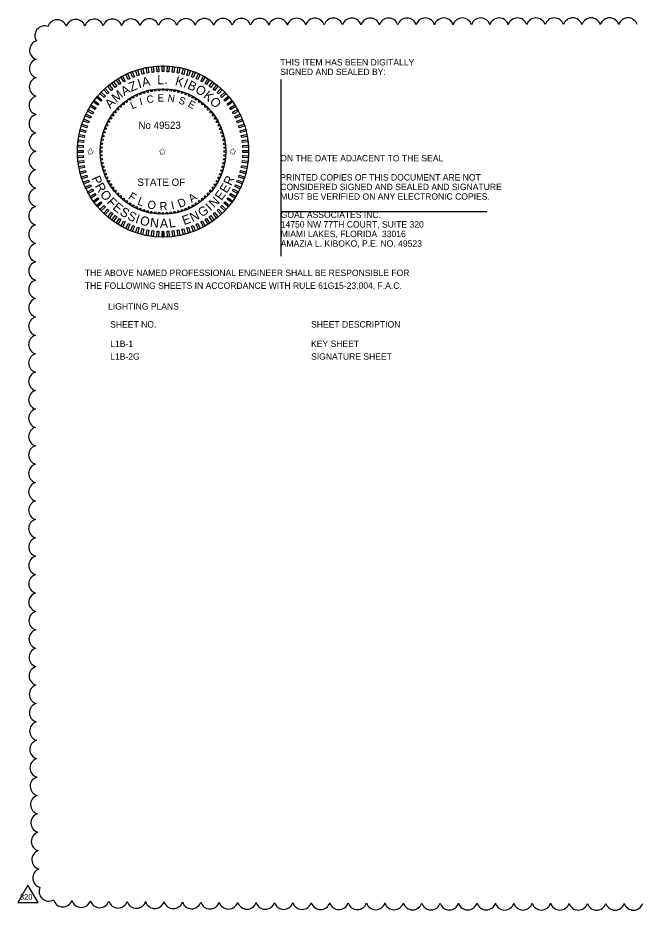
# Model space of a CAD drawing. Extents: x -811.2 to -767.6, y -2295.2 to -2235.1.
# Drawn here: x -783.8 to -777.02, y -2269.67 to -2259.9 of the extents above; entities that cross this region are included whole.
import ezdxf

# ---------------------------------------------------------------- set-up
doc = ezdxf.new("R2010")
doc.units = 0
for name, color, linetype in [('AdhocPoint_dp', 7, 'Continuous'), ('Cloud_dp', 7, 'Continuous'), ('PlotBorder_dp', 7, 'Continuous'), ('TextMinor', 7, 'Continuous'), ('TextMisc', 7, 'Continuous'), ('TextShtNo', 7, 'Continuous')]:
    doc.layers.add(name, color=color, linetype=linetype)

msp = doc.modelspace()

# ---------------------------------------------------------------- linework, layer by layer
at = {"layer": 'AdhocPoint_dp'}
for p, q in [((-780.9186, -2260.5734), (-780.9186, -2262.5081)), ((-780.9186, -2262.0181), (-778.6618, -2262.0181))]:
    msp.add_line(p, q, dxfattribs=at)
at = {"layer": 'Cloud_dp'}
msp.add_lwpolyline([(-783.6889, -2269.3954), (-783.7966, -2269.5835), (-783.576, -2269.5835)], close=True, dxfattribs=at)
for centre, start, end in [((-782.5594, -2260.0139), 17.87787, 162.87787), ((-782.3579, -2260.0127), 17.82689, 162.82689), ((-782.1564, -2260.0116), 17.78716, 162.78716), ((-781.9548, -2260.0107), 17.75505, 162.75505), ((-781.7533, -2260.0098), 17.72841, 162.72841), ((-781.5518, -2260.009), 17.70584, 162.70584), ((-781.3502, -2260.0084), 17.6864, 162.6864), ((-781.1487, -2260.0077), 17.66942, 162.66942), ((-780.9472, -2260.0072), 17.65443, 162.65443), ((-780.7456, -2260.0066), 17.64106, 162.64106), ((-780.5441, -2260.0062), 17.62905, 162.62905), ((-780.3425, -2260.0057), 17.61817, 162.61817), ((-780.141, -2260.0053), 17.60826, 162.60826), ((-779.9394, -2260.005), 17.59919, 162.59919), ((-779.7379, -2260.0046), 17.59084, 162.59084), ((-779.5364, -2260.0043), 17.58312, 162.58312), ((-779.3348, -2260.004), 17.57595, 162.57595), ((-779.1333, -2260.0038), 17.56928, 162.56928), ((-778.9317, -2260.0036), 17.56305, 162.56305), ((-778.7302, -2260.0033), 17.55721, 162.55721), ((-778.5286, -2260.0032), 17.55172, 162.55172), ((-778.3271, -2260.003), 17.54655, 162.54655), ((-778.1255, -2260.0028), 17.54167, 162.54167), ((-777.924, -2260.0027), 17.53705, 162.53705), ((-777.7224, -2260.0026), 17.53267, 162.53267), ((-777.5209, -2260.0025), 17.52851, 162.52851), ((-777.3194, -2260.0024), 17.52455, 162.52455), ((-777.1178, -2260.0023), 17.52079, 162.52079), ((-783.5053, -2260.0909), 68.43954, 213.43954), ((-783.3652, -2260.0225), 18.59454, 163.59454), ((-783.1638, -2260.0193), 18.21421, 163.21421), ((-782.9624, -2260.0171), 18.04696, 163.04696), ((-782.7609, -2260.0154), 17.94666, 162.94666), ((-783.563, -2260.2503), 106.80445, 251.80445), ((-783.565, -2260.4517), 107.04367, 252.04367), ((-783.5664, -2260.6532), 107.15618, 252.15618), ((-783.5675, -2260.8547), 107.22533, 252.22533), ((-783.5684, -2261.0562), 107.27338, 252.27338), ((-783.5691, -2261.2578), 107.30928, 252.30928), ((-783.5697, -2261.4593), 107.33743, 252.33743), ((-783.5703, -2261.6608), 107.36027, 252.36027), ((-783.5707, -2261.8624), 107.37928, 252.37928), ((-783.5711, -2262.0639), 107.39543, 252.39543), ((-783.5715, -2262.2655), 107.40937, 252.40937), ((-783.5717, -2262.467), 107.42156, 252.42156), ((-783.572, -2262.6685), 107.43234, 252.43234), ((-783.5722, -2262.8701), 107.44197, 252.44197), ((-783.5724, -2263.0716), 107.45063, 252.45063), ((-783.5726, -2263.2732), 107.45847, 252.45847), ((-783.5727, -2263.4747), 107.46563, 252.46563), ((-783.5728, -2263.6763), 107.47218, 252.47218), ((-783.5729, -2263.8778), 107.47822, 252.47822), ((-783.573, -2264.0794), 107.4838, 252.4838), ((-783.573, -2264.2809), 107.48899, 252.48899), ((-783.5731, -2264.4824), 107.49382, 252.49382), ((-783.5731, -2264.684), 107.49843, 252.49843), ((-783.573, -2264.8855), 107.51148, 252.51148), ((-783.573, -2265.0871), 107.53101, 252.53101), ((-783.5728, -2265.2886), 107.55191, 252.55191), ((-783.5726, -2265.4901), 107.57435, 252.57435), ((-783.5723, -2265.6917), 107.59852, 252.59852), ((-783.5719, -2265.8932), 107.62468, 252.62468), ((-783.5714, -2266.0947), 107.65309, 252.65309), ((-783.5708, -2266.2963), 107.68411, 252.68411), ((-783.5701, -2266.4978), 107.71817, 252.71817), ((-783.5693, -2266.6993), 107.75578, 252.75578), ((-783.5683, -2266.9009), 107.79762, 252.79762), ((-783.5672, -2267.1024), 107.84454, 252.84454), ((-783.5659, -2267.3039), 107.89767, 252.89767), ((-783.5644, -2267.5054), 107.95851, 252.95851), ((-783.5626, -2267.7069), 108.02912, 253.02912), ((-783.5606, -2267.9084), 108.11243, 253.11243), ((-783.5583, -2268.1099), 108.21279, 253.21279), ((-783.5556, -2268.3113), 108.33694, 253.33694), ((-783.5523, -2268.5128), 108.49611, 253.49611), ((-783.5485, -2268.7142), 108.71068, 253.71068), ((-783.5437, -2268.9155), 109.02298, 254.02298), ((-783.5374, -2269.1166), 109.54201, 254.54201), ((-783.5282, -2269.3173), 110.71007, 255.71007), ((-783.4585, -2269.4643), 155.06518, 300.06518), ((-783.3038, -2269.5272), 195.62937, 340.62937), ((-783.1027, -2269.5327), 196.26473, 341.26473), ((-782.9013, -2269.5365), 196.54985, 341.54985), ((-782.6999, -2269.5396), 196.72204, 341.72204), ((-782.4984, -2269.5421), 196.84059, 341.84059), ((-782.2969, -2269.5443), 196.92865, 341.92865), ((-782.0954, -2269.5461), 196.99739, 341.99739), ((-781.8939, -2269.5478), 197.053, 342.053), ((-781.6924, -2269.5493), 197.09919, 342.09919), ((-781.4909, -2269.5506), 197.13834, 342.13834), ((-781.2893, -2269.5519), 197.17209, 342.17209), ((-781.0878, -2269.553), 197.20158, 342.20158), ((-780.8863, -2269.554), 197.22762, 342.22762), ((-780.6847, -2269.5549), 197.25085, 342.25085), ((-780.4832, -2269.5557), 197.27174, 342.27174), ((-780.2817, -2269.5565), 197.29065, 342.29065), ((-780.0801, -2269.5572), 197.30788, 342.30788), ((-779.8786, -2269.5578), 197.32367, 342.32367), ((-779.6771, -2269.5584), 197.3382, 342.3382), ((-779.4755, -2269.559), 197.35163, 342.35163), ((-779.274, -2269.5595), 197.3641, 342.3641), ((-779.0724, -2269.5599), 197.37571, 342.37571), ((-778.8709, -2269.5604), 197.38657, 342.38657), ((-778.6693, -2269.5607), 197.39674, 342.39674), ((-778.4678, -2269.5611), 197.40629, 342.40629), ((-778.2663, -2269.5614), 197.4153, 342.4153), ((-778.0647, -2269.5617), 197.4238, 342.4238), ((-777.8632, -2269.5619), 197.43184, 342.43184), ((-777.6616, -2269.5622), 197.43947, 342.43947), ((-777.4601, -2269.5624), 197.44671, 342.44671), ((-777.2585, -2269.5625), 197.4536, 342.4536), ((-777.057, -2269.5627), 197.46017, 342.46017)]:
    msp.add_arc(centre, 0.1057, start, end, dxfattribs=at)
at = {"layer": 'TextMinor'}
for radius in [0.9375, 0.6875]:
    msp.add_circle((-782.2078, -2261.3603), radius, dxfattribs=at)
at = {"layer": 'TextShtNo'}
for p, q in [((-782.2178, -2262.2978), (-782.218, -2262.2353)), ((-782.2078, -2262.2978), (-782.208, -2262.2353)), ((-782.1978, -2262.2978), (-782.198, -2262.2353))]:
    msp.add_line(p, q, dxfattribs=at)
for points in [[(-782.5205, -2260.543), (-782.5392, -2260.5504), (-782.5622, -2260.4923), (-782.5434, -2260.4849)], [(-782.4685, -2260.525), (-782.4877, -2260.5312), (-782.507, -2260.4718), (-782.4878, -2260.4656)], [(-782.4156, -2260.5102), (-782.4351, -2260.5152), (-782.4506, -2260.4548), (-782.4311, -2260.4498)], [(-782.3618, -2260.4989), (-782.3816, -2260.5026), (-782.3933, -2260.4413), (-782.3735, -2260.4375)], [(-782.3074, -2260.4909), (-782.3274, -2260.4934), (-782.3352, -2260.4315), (-782.3152, -2260.4289)], [(-782.2526, -2260.4864), (-782.2727, -2260.4876), (-782.2767, -2260.4253), (-782.2565, -2260.424)], [(-782.1976, -2260.4853), (-782.2178, -2260.4853), (-782.2178, -2260.4228), (-782.1976, -2260.4228)], [(-782.1427, -2260.4876), (-782.1629, -2260.4864), (-782.1589, -2260.4241), (-782.1388, -2260.4253)], [(-782.088, -2260.4934), (-782.1081, -2260.4909), (-782.1002, -2260.429), (-782.0802, -2260.4315)], [(-782.0338, -2260.5027), (-782.0537, -2260.4989), (-782.042, -2260.4376), (-782.0221, -2260.4413)], [(-781.9803, -2260.5153), (-781.9999, -2260.5103), (-781.9844, -2260.4498), (-781.9648, -2260.4548)], [(-781.9277, -2260.5312), (-781.9469, -2260.525), (-781.9276, -2260.4656), (-781.9084, -2260.4719)], [(-781.8762, -2260.5505), (-781.895, -2260.543), (-781.872, -2260.485), (-781.8532, -2260.4924)], [(-782.6681, -2260.616), (-782.6851, -2260.6268), (-782.7186, -2260.5741), (-782.7015, -2260.5633)], [(-782.6204, -2260.5886), (-782.6381, -2260.5983), (-782.6682, -2260.5436), (-782.6505, -2260.5339)], [(-782.5712, -2260.5642), (-782.5894, -2260.5728), (-782.616, -2260.5163), (-782.5978, -2260.5077)], [(-781.826, -2260.5729), (-781.8443, -2260.5643), (-781.8177, -2260.5078), (-781.7994, -2260.5164)], [(-781.7773, -2260.5984), (-781.795, -2260.5887), (-781.7649, -2260.534), (-781.7473, -2260.5437)], [(-781.7303, -2260.6269), (-781.7474, -2260.6161), (-781.7139, -2260.5634), (-781.6969, -2260.5742)], [(-782.7994, -2260.7155), (-782.8141, -2260.7293), (-782.8568, -2260.6838), (-782.8421, -2260.6699)], [(-782.7577, -2260.6796), (-782.7733, -2260.6925), (-782.8131, -2260.6443), (-782.7975, -2260.6315)], [(-782.7139, -2260.6464), (-782.7302, -2260.6583), (-782.7669, -2260.6078), (-782.7506, -2260.5959)], [(-781.6852, -2260.6584), (-781.7016, -2260.6465), (-781.6649, -2260.596), (-781.6485, -2260.6079)], [(-781.6422, -2260.6926), (-781.6578, -2260.6797), (-781.618, -2260.6316), (-781.6024, -2260.6445)], [(-781.6014, -2260.7294), (-781.6161, -2260.7156), (-781.5734, -2260.6701), (-781.5586, -2260.6839)], [(-782.8755, -2260.7947), (-782.8884, -2260.8102), (-782.9365, -2260.7704), (-782.9237, -2260.7549)], [(-782.8387, -2260.7539), (-782.8525, -2260.7686), (-782.898, -2260.7258), (-782.8842, -2260.7111)], [(-781.563, -2260.7687), (-781.5768, -2260.754), (-781.5313, -2260.7113), (-781.5175, -2260.726)], [(-781.5271, -2260.8104), (-781.54, -2260.7948), (-781.4919, -2260.755), (-781.479, -2260.7706)], [(-782.9412, -2260.8828), (-782.952, -2260.8999), (-783.0047, -2260.8664), (-782.9939, -2260.8494)], [(-782.9097, -2260.8377), (-782.9216, -2260.8541), (-782.9721, -2260.8174), (-782.9603, -2260.801)], [(-781.4939, -2260.8542), (-781.5058, -2260.8379), (-781.4553, -2260.8012), (-781.4434, -2260.8175)], [(-781.4635, -2260.9), (-781.4744, -2260.883), (-781.4216, -2260.8495), (-781.4108, -2260.8666)], [(-782.9952, -2260.9785), (-783.0038, -2260.9968), (-783.0603, -2260.9702), (-783.0517, -2260.9519)], [(-782.9697, -2260.9298), (-782.9794, -2260.9475), (-783.0341, -2260.9174), (-783.0244, -2260.8997)], [(-781.4361, -2260.9477), (-781.4458, -2260.93), (-781.3911, -2260.8999), (-781.3814, -2260.9176)], [(-781.4117, -2260.9969), (-781.4203, -2260.9787), (-781.3638, -2260.9521), (-781.3552, -2260.9704)], [(-783.0369, -2261.0802), (-783.0431, -2261.0994), (-783.1025, -2261.0801), (-783.0963, -2261.0609)], [(-783.0176, -2261.0287), (-783.0251, -2261.0475), (-783.0831, -2261.0245), (-783.0757, -2261.0057)], [(-781.3905, -2261.0477), (-781.3979, -2261.0289), (-781.3399, -2261.0059), (-781.3324, -2261.0247)], [(-781.3725, -2261.0996), (-781.3787, -2261.0804), (-781.3193, -2261.0611), (-781.3131, -2261.0803)], [(-783.0654, -2261.1863), (-783.0692, -2261.2062), (-783.1306, -2261.1945), (-783.1268, -2261.1746)], [(-783.0528, -2261.1328), (-783.0578, -2261.1524), (-783.1183, -2261.1368), (-783.1133, -2261.1173)], [(-781.3577, -2261.1526), (-781.3628, -2261.133), (-781.3023, -2261.1175), (-781.2973, -2261.137)], [(-781.3464, -2261.2063), (-781.3502, -2261.1865), (-781.2888, -2261.1748), (-781.285, -2261.1946)], [(-783.0747, -2261.2405), (-783.0772, -2261.2606), (-783.1391, -2261.2527), (-783.1366, -2261.2327)], [(-781.3384, -2261.2607), (-781.3409, -2261.2407), (-781.279, -2261.2329), (-781.2765, -2261.2529)], [(-783.0828, -2261.3501), (-783.0828, -2261.3703), (-783.1453, -2261.3703), (-783.1453, -2261.3501)], [(-783.0805, -2261.2952), (-783.0817, -2261.3153), (-783.1441, -2261.3114), (-783.1428, -2261.2913)], [(-781.3339, -2261.3155), (-781.3351, -2261.2954), (-781.2728, -2261.2915), (-781.2716, -2261.3116)], [(-781.3328, -2261.3705), (-781.3328, -2261.3503), (-781.2703, -2261.3503), (-781.2703, -2261.3705)], [(-783.0818, -2261.4051), (-783.0805, -2261.4252), (-783.1428, -2261.4291), (-783.1441, -2261.409)], [(-783.0772, -2261.4599), (-783.0747, -2261.4799), (-783.1366, -2261.4877), (-783.1392, -2261.4677)], [(-781.341, -2261.4801), (-781.3384, -2261.4601), (-781.2765, -2261.4679), (-781.279, -2261.4879)], [(-781.3351, -2261.4254), (-781.3339, -2261.4053), (-781.2716, -2261.4092), (-781.2728, -2261.4293)], [(-783.0693, -2261.5143), (-783.0655, -2261.5341), (-783.1268, -2261.5458), (-783.1306, -2261.526)], [(-783.0579, -2261.568), (-783.0529, -2261.5876), (-783.1133, -2261.6031), (-783.1184, -2261.5836)], [(-781.3628, -2261.5878), (-781.3578, -2261.5682), (-781.2973, -2261.5838), (-781.3023, -2261.6033)], [(-781.3502, -2261.5343), (-781.3464, -2261.5144), (-781.2851, -2261.5261), (-781.2889, -2261.546)], [(-783.0432, -2261.621), (-783.0369, -2261.6402), (-783.0963, -2261.6595), (-783.1025, -2261.6403)], [(-781.3788, -2261.6404), (-781.3725, -2261.6212), (-781.3131, -2261.6405), (-781.3194, -2261.6597)], [(-783.0251, -2261.673), (-783.0177, -2261.6917), (-783.0758, -2261.7147), (-783.0832, -2261.6959)], [(-783.0039, -2261.7237), (-782.9953, -2261.7419), (-783.0518, -2261.7685), (-783.0604, -2261.7502)], [(-781.4204, -2261.7421), (-781.4118, -2261.7238), (-781.3553, -2261.7504), (-781.3639, -2261.7687)], [(-781.398, -2261.6919), (-781.3906, -2261.6731), (-781.3325, -2261.6961), (-781.3399, -2261.7149)], [(-782.9795, -2261.7729), (-782.9698, -2261.7906), (-783.0245, -2261.8207), (-783.0342, -2261.803)], [(-782.9521, -2261.8206), (-782.9413, -2261.8376), (-782.994, -2261.8711), (-783.0048, -2261.854)], [(-781.4745, -2261.8378), (-781.4636, -2261.8207), (-781.4109, -2261.8542), (-781.4217, -2261.8712)], [(-781.4459, -2261.7908), (-781.4362, -2261.7731), (-781.3815, -2261.8032), (-781.3912, -2261.8209)], [(-782.9217, -2261.8664), (-782.9099, -2261.8827), (-782.9604, -2261.9194), (-782.9722, -2261.9031)], [(-782.8885, -2261.9102), (-782.8757, -2261.9258), (-782.9238, -2261.9656), (-782.9366, -2261.95)], [(-782.8527, -2261.9519), (-782.8388, -2261.9666), (-782.8844, -2262.0093), (-782.8982, -2261.9946)], [(-781.5769, -2261.9667), (-781.5631, -2261.952), (-781.5176, -2261.9948), (-781.5314, -2262.0095)], [(-781.5401, -2261.9259), (-781.5272, -2261.9104), (-781.4791, -2261.9502), (-781.492, -2261.9657)], [(-781.5059, -2261.8829), (-781.494, -2261.8665), (-781.4435, -2261.9032), (-781.4554, -2261.9196)], [(-782.8142, -2261.9912), (-782.7995, -2262.005), (-782.8423, -2262.0505), (-782.857, -2262.0367)], [(-782.7734, -2262.028), (-782.7579, -2262.0409), (-782.7977, -2262.089), (-782.8132, -2262.0761)], [(-781.6579, -2262.041), (-781.6423, -2262.0281), (-781.6025, -2262.0763), (-781.6181, -2262.0891)], [(-781.6162, -2262.0051), (-781.6015, -2261.9913), (-781.5588, -2262.0368), (-781.5735, -2262.0507)], [(-782.7304, -2262.0622), (-782.7141, -2262.0741), (-782.7508, -2262.1246), (-782.7671, -2262.1127)], [(-782.6853, -2262.0937), (-782.6682, -2262.1045), (-782.7017, -2262.1572), (-782.7187, -2262.1464)], [(-782.6383, -2262.1222), (-782.6206, -2262.1319), (-782.6507, -2262.1866), (-782.6684, -2262.1769)], [(-782.5896, -2262.1477), (-782.5713, -2262.1563), (-782.5979, -2262.2128), (-782.6162, -2262.2042)], [(-781.8445, -2262.1564), (-781.8262, -2262.1478), (-781.7996, -2262.2043), (-781.8179, -2262.2129)], [(-781.7952, -2262.132), (-781.7775, -2262.1223), (-781.7474, -2262.177), (-781.7651, -2262.1867)], [(-781.7475, -2262.1046), (-781.7305, -2262.0938), (-781.697, -2262.1465), (-781.7141, -2262.1573)], [(-781.7017, -2262.0742), (-781.6854, -2262.0623), (-781.6487, -2262.1129), (-781.665, -2262.1247)], [(-782.5394, -2262.1701), (-782.5206, -2262.1776), (-782.5436, -2262.2356), (-782.5624, -2262.2282)], [(-782.4879, -2262.1894), (-782.4687, -2262.1956), (-782.488, -2262.255), (-782.5072, -2262.2487)], [(-782.4353, -2262.2053), (-782.4157, -2262.2103), (-782.4313, -2262.2708), (-782.4508, -2262.2658)], [(-782.3818, -2262.2179), (-782.362, -2262.2217), (-782.3737, -2262.283), (-782.3935, -2262.2793)], [(-782.3276, -2262.2272), (-782.3076, -2262.2297), (-782.3154, -2262.2916), (-782.3354, -2262.2891)], [(-782.2729, -2262.233), (-782.2528, -2262.2342), (-782.2567, -2262.2966), (-782.2768, -2262.2953)], [(-782.218, -2262.2353), (-782.1978, -2262.2353), (-782.1978, -2262.2978), (-782.218, -2262.2978)], [(-782.163, -2262.2342), (-782.1429, -2262.233), (-782.139, -2262.2953), (-782.1591, -2262.2966)], [(-782.1082, -2262.2297), (-782.0882, -2262.2272), (-782.0804, -2262.2891), (-782.1004, -2262.2917)], [(-782.0539, -2262.2217), (-782.034, -2262.218), (-782.0223, -2262.2793), (-782.0422, -2262.2831)], [(-782.0001, -2262.2104), (-781.9805, -2262.2054), (-781.965, -2262.2658), (-781.9845, -2262.2709)], [(-781.9471, -2262.1957), (-781.9279, -2262.1894), (-781.9086, -2262.2488), (-781.9278, -2262.255)], [(-781.8952, -2262.1776), (-781.8764, -2262.1702), (-781.8534, -2262.2283), (-781.8722, -2262.2357)]]:
    msp.add_lwpolyline(points, close=True, dxfattribs=at)
for centre in [(-782.3342, -2260.6947), (-782.2922, -2260.6881), (-782.2498, -2260.6841), (-782.2072, -2260.6828), (-782.1647, -2260.6842), (-782.1223, -2260.6882), (-782.0803, -2260.6949), (-782.5703, -2260.788), (-782.5337, -2260.7664), (-782.4958, -2260.7471), (-782.4567, -2260.7302), (-782.4166, -2260.7158), (-782.3757, -2260.704), (-782.0388, -2260.7043), (-781.9979, -2260.7162), (-781.9579, -2260.7306), (-781.9189, -2260.7476), (-781.8809, -2260.7669), (-781.8443, -2260.7886), (-782.7013, -2260.8961), (-782.6712, -2260.8661), (-782.6392, -2260.8379), (-782.6056, -2260.8119), (-781.8092, -2260.8125), (-781.7755, -2260.8387), (-781.7436, -2260.8668), (-782.7556, -2260.9616), (-782.7295, -2260.928), (-781.7136, -2260.897), (-781.6855, -2260.9289), (-781.6594, -2260.9626), (-782.8206, -2261.0713), (-782.8012, -2261.0334), (-782.7795, -2260.9968), (-781.6355, -2260.9978), (-781.6139, -2261.0344), (-781.5946, -2261.0724), (-782.852, -2261.1504), (-782.8375, -2261.1104), (-781.5777, -2261.1114), (-781.5633, -2261.1515), (-782.8799, -2261.2748), (-782.8732, -2261.2328), (-782.8639, -2261.1913), (-781.5515, -2261.1924), (-781.5422, -2261.2339), (-781.5356, -2261.276), (-782.8853, -2261.3597), (-782.8839, -2261.3172), (-781.5316, -2261.3183), (-781.5303, -2261.3609), (-782.884, -2261.4023), (-782.88, -2261.4447), (-781.5358, -2261.4458), (-781.5317, -2261.4034), (-782.8734, -2261.4867), (-782.8641, -2261.5282), (-782.8523, -2261.5691), (-781.5637, -2261.5702), (-781.5518, -2261.5293), (-781.5425, -2261.4878), (-782.8379, -2261.6092), (-782.821, -2261.6482), (-781.5951, -2261.6493), (-781.5781, -2261.6102), (-782.8018, -2261.6862), (-782.7801, -2261.7228), (-782.7562, -2261.7581), (-781.6601, -2261.759), (-781.6361, -2261.7238), (-781.6144, -2261.6872), (-782.7302, -2261.7917), (-782.7021, -2261.8236), (-782.672, -2261.8538), (-781.7445, -2261.8545), (-781.7143, -2261.8245), (-781.6862, -2261.7926), (-782.6401, -2261.8819), (-782.6065, -2261.9081), (-782.5713, -2261.932), (-782.5347, -2261.9537), (-781.8819, -2261.9542), (-781.8453, -2261.9326), (-781.8101, -2261.9087), (-781.7764, -2261.8827), (-782.4968, -2261.9731), (-782.4577, -2261.99), (-782.4177, -2262.0044), (-782.3768, -2262.0163), (-782.3353, -2262.0257), (-782.2933, -2262.0324), (-782.2509, -2262.0364), (-782.2078, -2262.0378), (-782.1658, -2262.0365), (-782.1235, -2262.0325), (-782.0814, -2262.0259), (-782.0399, -2262.0166), (-781.999, -2262.0048), (-781.9589, -2261.9904), (-781.9199, -2261.9735)]:
    msp.add_circle(centre, 0.01, dxfattribs=at)

# ---------------------------------------------------------------- texts
at = {"layer": 'Cloud_dp'}
msp.add_text('320', height=0.05998, rotation=0, dxfattribs=at).set_placement((-783.7746, -2269.5534))
at = {"layer": 'PlotBorder_dp'}
for s, height, p in [('THIS ITEM HAS BEEN DIGITALLY', 0.07, (-780.9235, -2260.4183)), ('SIGNED AND SEALED BY:', 0.07, (-780.9235, -2260.5233)), ('No 49523', 0.08, (-782.4768, -2261.1131)), ('ON THE DATE ADJACENT TO THE SEAL', 0.07, (-780.9235, -2261.4683)), ('STATE OF', 0.08, (-782.4875, -2261.7365)), ('PRINTED COPIES OF THIS DOCUMENT ARE NOT ', 0.07, (-780.9235, -2261.6783)), ('CONSIDERED SIGNED AND SEALED AND SIGNATURE ', 0.07, (-780.9235, -2261.7833)), ('MUST BE VERIFIED ON ANY ELECTRONIC COPIES.', 0.07, (-780.9235, -2261.8883)), ('GOAL ASSOCIATES INC.', 0.07, (-780.9186, -2262.0881)), ('14750 NW 77TH COURT, SUITE 320', 0.07, (-780.9186, -2262.1931)), ('MIAMI LAKES, FLORIDA  33016', 0.07, (-780.9186, -2262.2981)), ('AMAZIA L. KIBOKO, P.E. NO. 49523', 0.07, (-780.9186, -2262.4031)), ('THE ABOVE NAMED PROFESSIONAL ENGINEER SHALL BE RESPONSIBLE FOR ', 0.07, (-783.0626, -2262.7243)), ('THE FOLLOWING SHEETS IN ACCORDANCE WITH RULE 61G15-23.004, F.A.C.', 0.07, (-783.0626, -2262.8643)), ('LIGHTING PLANS', 0.07, (-782.8089, -2263.0913))]:
    msp.add_text(s, height=height, dxfattribs=at).set_placement(p)
for s, height, rotation, p in [('Z', 0.1, 23.30524, (-782.5548, -2260.707)), ('I', 0.1, 17.68363, (-782.4679, -2260.6694)), ('A', 0.1, 11.91844, (-782.4286, -2260.6534)), ('L', 0.1, 359.96623, (-782.2714, -2260.623)), ('K', 0.1, 344.27273, (-782.0807, -2260.6302)), ('I', 0.1, 337.77772, (-781.9921, -2260.652)), ('B', 0.1, 334.48695, (-781.9482, -2260.6673)), ('M', 0.1, 39.30005, (-782.7212, -2260.8277)), ('A', 0.1, 31.46601, (-782.6322, -2260.7556)), ('.', 0.1, 353.78581, (-782.1947, -2260.6201)), ('O', 0.1, 327.82385, (-781.8635, -2260.7059)), ('K', 0.1, 321.0594, (-781.7739, -2260.7631)), ('O', 0.1, 314.20329, (-781.7043, -2260.8207)), ('A', 0.1, 46.80938, (-782.7835, -2260.8962)), ('P', 0.1, 293.19548, (-782.9935, -2261.6519)), ('R', 0.1, 65.28865, (-781.4614, -2261.7412)), ('R', 0.1, 300.25949, (-782.9566, -2261.7378)), ('E', 0.1, 58.61694, (-781.5106, -2261.8252)), ('O', 0.1, 307.26617, (-782.9025, -2261.8296)), ('F', 0.1, 314.20329, (-782.8291, -2261.9221)), ('F', 0.09, 328.53399, (-782.5962, -2261.8756)), ('L', 0.09, 339.48752, (-782.495, -2261.9386)), ('A', 0.09, 35.54629, (-781.8934, -2261.9249)), ('N', 0.1, 44.34211, (-781.6479, -2261.9838)), ('E', 0.1, 53.99864, (-781.5679, -2261.9039)), ('E', 0.1, 321.0594, (-782.7657, -2261.9857)), ('O', 0.09, 348.08156, (-782.3856, -2261.9792)), ('R', 0.09, 3.10738, (-782.2434, -2262.0054)), ('I', 0.09, 12.52485, (-782.1092, -2261.9963)), ('D', 0.09, 22.22228, (-782.0251, -2261.9794)), ('G', 0.1, 34.11362, (-781.7834, -2262.084)), ('I', 0.1, 41.83906, (-781.6873, -2262.018)), ('S', 0.1, 327.82385, (-782.6895, -2262.0462)), ('S', 0.1, 334.48695, (-782.6064, -2262.0976)), ('I', 0.1, 341.03996, (-782.5178, -2262.1389)), ('E', 0.1, 20.51248, (-781.9761, -2262.1675)), ('N', 0.1, 26.0618, (-781.8846, -2262.1342)), ('O', 0.1, 344.27273, (-782.4687, -2262.1565)), ('N', 0.1, 353.78581, (-782.3543, -2262.1864)), ('A', 0.1, 359.96623, (-782.242, -2262.1974)), ('L', 0.1, 8.98261, (-782.1363, -2262.1966))]:
    msp.add_text(s, height=height, rotation=rotation, dxfattribs=at).set_placement(p)
at = {"layer": 'TextMisc'}
for s, p in [('SHEET NO.', (-782.7855, -2263.2883)), ('SHEET DESCRIPTION', (-780.5865, -2263.2883)), ('L1B-1', (-782.7855, -2263.5005)), ('KEY SHEET', (-780.5865, -2263.5005)), ('L1B-2G', (-782.7855, -2263.6405)), ('SIGNATURE SHEET', (-780.5865, -2263.6405))]:
    msp.add_text(s, height=0.07, dxfattribs=at).set_placement(p)
at = {"layer": 'TextShtNo'}
for s, rotation, p in [('I', 14.81888, (-782.4534, -2260.8551)), ('C', 8.98261, (-782.3808, -2260.8324)), ('E', 359.96623, (-782.2681, -2260.8135)), ('N', 350.64643, (-782.1612, -2260.8121)), ('S', 341.03996, (-782.0441, -2260.8309)), ('L', 23.30524, (-782.544, -2260.898)), ('E', 331.16864, (-781.9426, -2260.8635))]:
    msp.add_text(s, height=0.08, rotation=rotation, dxfattribs=at).set_placement(p)
for p in [(-783.0428, -2261.3983), (-782.2581, -2261.3983), (-781.4862, -2261.3983)]:
    msp.add_text('✩', height=0.08, dxfattribs=at).set_placement(p)

doc.saveas('drawing.dxf')
